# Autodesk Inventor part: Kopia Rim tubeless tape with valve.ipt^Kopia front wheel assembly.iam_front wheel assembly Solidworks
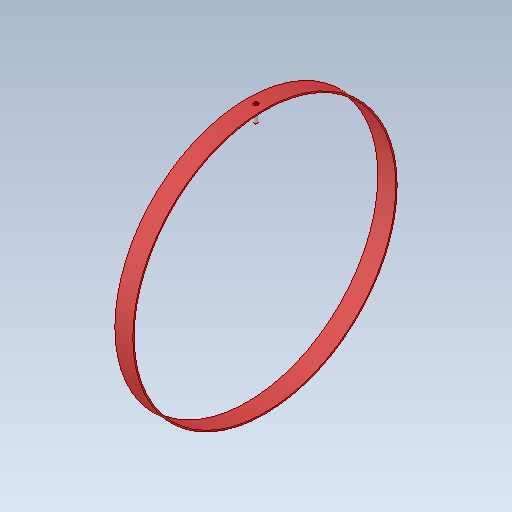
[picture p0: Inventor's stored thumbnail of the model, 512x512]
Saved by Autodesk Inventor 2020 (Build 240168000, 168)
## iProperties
Created: 2017-09
Part Number: Kopia Rim tubeless tape with valve.ipt^Kopia front wheel assembly.iam_front wheel assembly Solidworks
Material: Ogólny
Document SubType Name: Modeling
Designer: Tomasz
Density: 1 g/cm^3
Appearance: Domyślna
Sending System: SolidWorks 2017
Last Author: Tomasz
Last Saved: 2017-09-11
Author: Tomasz
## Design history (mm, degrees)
feature "Rim tubeless tape with valve.ipt"
node "Bryła1"
